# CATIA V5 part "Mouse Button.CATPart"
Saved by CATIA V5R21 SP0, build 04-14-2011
Part number: Mouse Button
Bounding box of the stored display mesh (mm): x 24.032 to 59.727, y -30.482 to 25.591, z 5.205 to 22.524
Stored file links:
  C:\CATIA V5_2015\ASD\Mouse Assembly Template\Mouse Button.CATPart
  C:\CATIA V5_2015\ASD\Mouse Assembly Template\Mouse Assembly Template.CATProduct
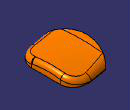
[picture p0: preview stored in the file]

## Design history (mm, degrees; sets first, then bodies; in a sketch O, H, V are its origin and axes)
External parameters (linked from other documents)
  `External.Mouse Front Radius Value` = 4 mm
  `External.Mouse Rear Radius Value` = 15 mm
Set1
  Sketch1 "Mouse Main Sketch", origin (0, 0, 0), H (1, 0, 0), V (0, 1, 0), geometry linked from another document
  DatumSurface1 "Top Surface": linked copy from another document
  Sketch2 "Mouse Button Sketch02", origin (0, 0, 0), H (1, 0, 0), V (0, 0, 1), geometry linked from another document
  Sketch3 "Mouse Button Sketch01", origin (0, 0, 0), H (1, 0, 0), V (0, 1, 0), geometry linked from another document
Set2 "Mouse Button Surface"
  Set3 "Button Cavity Body"
    Set4 "Operation Body"
      Trim1: Trimmed (Sweep1; DatumSurface1)
      Sweep1: type Segment, GuideCrv Sketch1, Length1 40, Length2 0, Angle 3, DraftDirection xy-plane
    Fillet1 "Final Cavity Surface": on edge [face of DatumSurface1 | face of Sweep1]
  Set5 "Button Core Body"
    Set6 "Operation Body"
      Extrude1: Element1 Sketch2, Lim1 40, Lim2 40
      Sweep2: type Segment, GuideCrv Sketch3, Length1 40, Length2 0, Angle 3, DraftDirection xy-plane
      Offset1: Offset Extrude1, Length 0.2
      Offset2: Offset Sweep2, Length 0.2
      Offset3: Offset Fillet1, Length 1
    Trim2 "Final Core Surface": Trimmed (Offset1; Offset2; Offset3)
  Trim3 "Final Button Surface": Trimmed (Fillet1; Trim2)
Body1 (main body)
  Body2
    CloseSurface1: CloseElement Trim3
  Assemble1: tool Body2
Relations
  `Fillet1.nls://PartDesignNLS/Radius` = `External.Mouse Front Radius Value`
  `Fillet1.nls://PartDesignNLS/Radius` = `External.Mouse Rear Radius Value`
